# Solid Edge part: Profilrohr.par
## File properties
Username: ahadarics
Dokumentum tartalom típus: 0
Author: ahadarics
Last saved by: ahadarics
Revision: 79
Sűrűség: 0,000 kg/m^3
Pontosság: 0,990
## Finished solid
Body 1: solid body, 6 faces, 6 edges, 0 vertices.
  Faces by surface: cone 2, cylinder 2, plane 2
  Edges by curve: circle 6
Bounding box of the edges (mm): 21.270 x 21.270 x 112.000, from (-10.635, -10.635, -91) to (10.635, 10.635, 21).
Cylindrical faces by radius (mm): R10 x1, R10.635 x1
Conical faces (half-angle, radius in mm at the cone's reference point): 15 deg R10.067 x2
Planar faces by outward normal: +z 1, -z 1
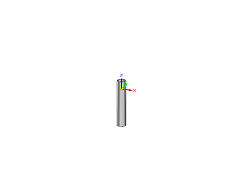
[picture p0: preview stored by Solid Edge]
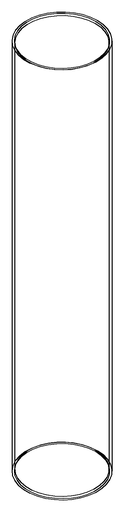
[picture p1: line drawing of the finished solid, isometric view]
